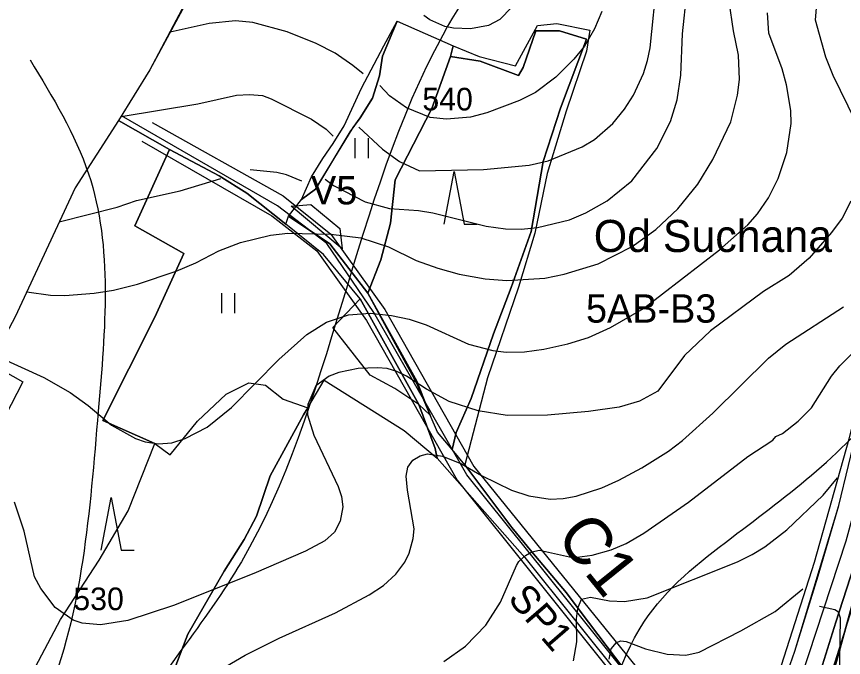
# Model space of a CAD drawing. Extents: x -684583 to -680383, y -1157874 to -1154904.
# Drawn here: x -683060.3 to -682621.9, y -1155712.7 to -1155373 of the extents above; entities that cross this region are included whole.
import ezdxf

# ---------------------------------------------------------------- set-up
doc = ezdxf.new("R2010")
doc.units = 0
for name, color, linetype in [('01_DOPRAVA', 7, 'Continuous'), ('01_MÍSTNÍ_NÁZVY', 7, 'Continuous'), ('01_OBVOD PÚ', 7, 'Continuous'), ('01_SPRÁV_HRANICE', 7, 'Continuous'), ('01_VRSTEVNICE', 7, 'Continuous'), ('02_KULTURY STAV', 7, 'Continuous'), ('03_PC_OBJEKTY_NÁVRH', 7, 'Continuous'), ('03_PC_POPIS_STAV', 7, 'Continuous'), ('03_PC_STAV', 7, 'Continuous'), ('05_VHO_MELIORACE', 7, 'Continuous'), ('06_BIOGEOGRAFIE', 7, 'Continuous'), ('06_ÚSES_IP', 7, 'Continuous')]:
    doc.layers.add(name, color=color, linetype=linetype)

msp = doc.modelspace()

# ---------------------------------------------------------------- linework, layer by layer
at = {"layer": '01_DOPRAVA'}
msp.add_lwpolyline([(-682444.78, -1155001.44), (-682484.97, -1155081.41), (-682523.81, -1155212.27), (-682554.69, -1155333.36), (-682575.58, -1155465.36), (-682603.29, -1155587.36), (-682620.55, -1155650.97), (-682668.34, -1155796.22), (-682702.3, -1155906.34), (-682764.53, -1156097.63), (-682782.62, -1156147.93)], dxfattribs=at)
at = {"layer": '01_OBVOD PÚ'}
msp.add_lwpolyline([(-682967.81, -1155360.67), (-682989.69, -1155401.27), (-683006.2, -1155428.07), (-683029.21, -1155463.74), (-683061.11, -1155532.25)], dxfattribs=at)
at = {"layer": '01_SPRÁV_HRANICE'}
msp.add_lwpolyline([(-682967.81, -1155360.67), (-682989.69, -1155401.27), (-683006.2, -1155428.07), (-683029.21, -1155463.74), (-683061.11, -1155532.25)], dxfattribs=at)
at = {"layer": '01_VRSTEVNICE'}
for points in [[(-682878.89, -1155431.61), (-682866.34, -1155443.3), (-682857.21, -1155449.86), (-682846.65, -1155454.71), (-682812.7, -1155454), (-682788.45, -1155451.72), (-682778.47, -1155449.58), (-682760.49, -1155442.02), (-682753.79, -1155438.17), (-682744.23, -1155429.75), (-682737.96, -1155422.19), (-682733.11, -1155414.63), (-682727.83, -1155403.22), (-682725.69, -1155396.37), (-682724.41, -1155389.53), (-682720.7, -1155353.01)], [(-682896.72, -1155459.28), (-682892.3, -1155462.56), (-682875.47, -1155471.26), (-682862.63, -1155474.68), (-682847.22, -1155475.82), (-682839.52, -1155477.11), (-682811.28, -1155484.1), (-682801.01, -1155485.53), (-682792.73, -1155485.67), (-682784.17, -1155484.81), (-682767.06, -1155480.82), (-682758.5, -1155477.11), (-682747.09, -1155470.69), (-682734.1, -1155460.13), (-682720.84, -1155442.88), (-682713.57, -1155428.61), (-682710, -1155417.2), (-682708.14, -1155404.08), (-682707.15, -1155382.11), (-682704.86, -1155360.43)], [(-683054.89, -1155518.9), (-683042.36, -1155520.76), (-683034.66, -1155520.9), (-683019.25, -1155519.62), (-683008.98, -1155518.05), (-682996.14, -1155514.91), (-682975.6, -1155507.92), (-682965.33, -1155503.5), (-682953.06, -1155497.22), (-682941.65, -1155492.8), (-682925.68, -1155488.81), (-682916.55, -1155487.81), (-682893.72, -1155488.38), (-682877.75, -1155490.23), (-682863.06, -1155495.08), (-682848.36, -1155502.36), (-682836.95, -1155506.35), (-682825.54, -1155509.49), (-682811.85, -1155512.06), (-682800.43, -1155512.91), (-682780.18, -1155511.63), (-682769.91, -1155509.49), (-682751.94, -1155504.07), (-682733.96, -1155494.94), (-682721.27, -1155485.95), (-682709.71, -1155474.97), (-682699.01, -1155461.85), (-682691.17, -1155448.87), (-682681.61, -1155428.9), (-682678.05, -1155414.63), (-682676.91, -1155406.36), (-682677.48, -1155393.52), (-682680.19, -1155380.68), (-682682.47, -1155364.99)], [(-682749.94, -1155370.41), (-682753.79, -1155379.54), (-682759.21, -1155388.67), (-682764.77, -1155395.66), (-682774.33, -1155405.07), (-682785.17, -1155413.21), (-682793.59, -1155417.48), (-682810.99, -1155424.05), (-682819.55, -1155426.33), (-682832.39, -1155427.47), (-682840.95, -1155426.47), (-682853.5, -1155421.33), (-682862.48, -1155415.06), (-682867.62, -1155409.5)], [(-682797.72, -1155367.99), (-682804.14, -1155374.55), (-682810.13, -1155377.69), (-682819.55, -1155379.54), (-682828.68, -1155379.26), (-682833.24, -1155378.26), (-682841.23, -1155374.83), (-682844.37, -1155372.55)], [(-682800.72, -1155550.86), (-682791.02, -1155550.71), (-682780.75, -1155549.29), (-682768.05, -1155546.43), (-682757.07, -1155543.15), (-682745.37, -1155537.88), (-682727.97, -1155527.75), (-682687.6, -1155496.65), (-682672.63, -1155483.39), (-682667.49, -1155477.54), (-682661.64, -1155469.12), (-682656.51, -1155458.85), (-682651.94, -1155445.16), (-682649.52, -1155429.75), (-682649.8, -1155422.9), (-682652.08, -1155409.21), (-682654.37, -1155400.65), (-682661.36, -1155381.82), (-682662.07, -1155370.98)], [(-682636.25, -1155368.56), (-682636.82, -1155374.83), (-682631.4, -1155394.38), (-682627.41, -1155404.08), (-682615.71, -1155428.32)], [(-682876.57, -1155403.42), (-682881.92, -1155398.9), (-682891.3, -1155392.38), (-682901.43, -1155387.24), (-682916.83, -1155381.11), (-682935.09, -1155376.26), (-682944.22, -1155375.26), (-682958.2, -1155376.69), (-682978.9, -1155381.25)], [(-683004.92, -1155425.98), (-682964.19, -1155419.34), (-682943.65, -1155414.77), (-682936.8, -1155414.35), (-682929.96, -1155414.92), (-682925.39, -1155416.63), (-682903.85, -1155427.47), (-682896.15, -1155432.75), (-682892.44, -1155436.46)], [(-682908.99, -1155460.28), (-682917.12, -1155457), (-682922.25, -1155455.71), (-682936.38, -1155454.29)], [(-683037.65, -1155481.88), (-683006.98, -1155474.11), (-682996.71, -1155470.55), (-682973.6, -1155465.41), (-682952.07, -1155458.85)], [(-682617.99, -1155470.83), (-682622.56, -1155479.96), (-682628.12, -1155487.52), (-682640.1, -1155501.07), (-682650.66, -1155510.35), (-682664.21, -1155518.76), (-682692.29, -1155539.65), (-682706.15, -1155552.71), (-682720.27, -1155571.54), (-682729.97, -1155576.82), (-682740.81, -1155579.96), (-682757.07, -1155582.38), (-682778.75, -1155584.23), (-682800.15, -1155584.38), (-682815.55, -1155581.95), (-682830.96, -1155577.1), (-682842.94, -1155570.54), (-682853.5, -1155563.69), (-682858.63, -1155561.13), (-682863.77, -1155559.56), (-682868.9, -1155559.13), (-682879.17, -1155559.56), (-682889.45, -1155561.7), (-682894.58, -1155563.69), (-682901.57, -1155568.69), (-682905.85, -1155578.67), (-682905.99, -1155584.09), (-682902.71, -1155594.93), (-682889.73, -1155622.04), (-682888.02, -1155627.46), (-682887.3, -1155632.88), (-682888.64, -1155640.39), (-682891.73, -1155646.36), (-682896.87, -1155650.89), (-682907.13, -1155656.41), (-682934.52, -1155668.11), (-682977.03, -1155685.08), (-683001.28, -1155693.07), (-683015.83, -1155695.35), (-683025.53, -1155694.5), (-683030.38, -1155692.93), (-683039.79, -1155686.23), (-683047.49, -1155676.1), (-683050.78, -1155669.96), (-683056.2, -1155645.71), (-683061.47, -1155630.31)], [(-682964.76, -1155726.45), (-682939.08, -1155711.47), (-682921.11, -1155702.49), (-682891.16, -1155689.08), (-682873.33, -1155679.52), (-682865.77, -1155674.53), (-682859.2, -1155668.54), (-682854.5, -1155662.26), (-682852.07, -1155657.41), (-682849.93, -1155649.71), (-682849.5, -1155644.57), (-682853.07, -1155624.03), (-682853.64, -1155616.61), (-682852.93, -1155611.76), (-682850.22, -1155608.06), (-682846.37, -1155605.77), (-682842.37, -1155604.78), (-682834.38, -1155606.06), (-682824.4, -1155610.05), (-682813.84, -1155616.19), (-682797.87, -1155624.03), (-682788.74, -1155627.03), (-682777.33, -1155628.88), (-682770.48, -1155628.46), (-682763.63, -1155627.17), (-682749.94, -1155622.75), (-682740.95, -1155618.75), (-682728.68, -1155612.19), (-682714.71, -1155603.35), (-682707.15, -1155597.64), (-682691.17, -1155583.24), (-682661.64, -1155554.14), (-682652.37, -1155546.58), (-682621.84, -1155526.89)], [(-683072, -1155552.54), (-683045.78, -1155564.26), (-683031.95, -1155572.25), (-683022.39, -1155579.24), (-683009.98, -1155589.51), (-682997.28, -1155596.64), (-682992.15, -1155598.36), (-682985.02, -1155599.5), (-682978.03, -1155598.93), (-682970.89, -1155596.64), (-682959.2, -1155590.65), (-682946.36, -1155580.24), (-682921.25, -1155554.85), (-682906.42, -1155541.58), (-682896.01, -1155535.02), (-682884.31, -1155531.03), (-682872.9, -1155530.17), (-682861.49, -1155531.46), (-682852.21, -1155533.45), (-682843.08, -1155536.45), (-682820.69, -1155546.58), (-682807.85, -1155550), (-682800.72, -1155550.86)], [(-682833.67, -1155714.75), (-682822.26, -1155706.62), (-682811.56, -1155695.5), (-682803.72, -1155683.37), (-682795.3, -1155663.97), (-682794.02, -1155661.83), (-682790.45, -1155658.7), (-682787.03, -1155656.7), (-682783.03, -1155655.84), (-682767.06, -1155659.27), (-682763.06, -1155659.55), (-682755.07, -1155658.55), (-682745.09, -1155655.7), (-682737.1, -1155652.28), (-682727.69, -1155646.86), (-682704.01, -1155630.31), (-682672.63, -1155606.2), (-682659.36, -1155597.5), (-682657.65, -1155595.65), (-682654.22, -1155594.08), (-682645.81, -1155587.52), (-682638.82, -1155580.38), (-682628.12, -1155563.55), (-682623.84, -1155558.13), (-682614.57, -1155549)], [(-682764.92, -1155714.47), (-682763.2, -1155704.48), (-682763.49, -1155692.22), (-682762.78, -1155686.65), (-682760.78, -1155681.8), (-682755.93, -1155680.66), (-682745.95, -1155682.66), (-682737.96, -1155682.95), (-682725.97, -1155681.09), (-682678.05, -1155661.98), (-682670.2, -1155658.12), (-682663.5, -1155653.99), (-682651.94, -1155645), (-682632.67, -1155626.7), (-682625.05, -1155617.54)], [(-682746.07, -1155713.51), (-682745.09, -1155708.19), (-682742.24, -1155704.77), (-682739.95, -1155703.91), (-682737.1, -1155704.2), (-682726.83, -1155708.19), (-682715.42, -1155710.9), (-682705.43, -1155711.47), (-682698.44, -1155709.9), (-682676.19, -1155698.63), (-682658.08, -1155688.36), (-682643.38, -1155676.24)], [(-682623.98, -1155726.45), (-682623.41, -1155691.93), (-682624.41, -1155688.65), (-682626.41, -1155687.51), (-682634.54, -1155685.65)]]:
    msp.add_lwpolyline(points, dxfattribs=at)
at = {"layer": '02_KULTURY STAV'}
for points in [[(-682954.04, -1155334.16), (-682989.69, -1155401.27), (-683006.2, -1155428.07), (-682979.18, -1155443.54), (-682952.96, -1155457.49), (-682938.17, -1155466.61), (-682917.62, -1155483.01), (-682916.12, -1155478.76), (-682909.29, -1155470.06), (-682903.85, -1155457.96), (-682897.92, -1155448.34), (-682892.38, -1155440.35), (-682886.65, -1155430.96), (-682877.39, -1155410.94), (-682865.59, -1155388.54), (-682858.57, -1155375.5), (-682828.85, -1155388.48), (-682815.01, -1155394.17), (-682795.71, -1155399.1), (-682784.17, -1155377.72), (-682773.85, -1155376.65), (-682756.27, -1155380.27), (-682758.16, -1155391.39), (-682768.88, -1155423.13), (-682778.99, -1155456.14), (-682785.42, -1155487.75), (-682794.08, -1155516.53), (-682810.62, -1155564.48), (-682822.56, -1155610.59), (-682797.64, -1155643.87), (-682787.07, -1155656.7), (-682768.66, -1155678.49), (-682761.91, -1155687.44), (-682732.92, -1155725.98)], [(-682666.12, -1155762.26), (-682647.64, -1155709.29), (-682635.27, -1155669.44), (-682624.39, -1155632.23), (-682608.85, -1155568.57), (-682591.9, -1155497.49), (-682584.57, -1155462.64), (-682579.29, -1155422.44), (-682571.28, -1155382.11), (-682563.38, -1155332.6)], [(-682647.1, -1155761.89), (-682625.87, -1155693.99), (-682606.64, -1155634.44), (-682588.52, -1155559.14), (-682573.81, -1155489.54), (-682560.88, -1155424.9), (-682555.58, -1155385.09), (-682547.5, -1155336.35)], [(-682880.89, -1155437.5), (-682880.89, -1155448)], [(-682873.89, -1155437.5), (-682873.89, -1155448)], [(-682833.51, -1155483.12), (-682828.26, -1155455.12), (-682823.01, -1155483.12), (-682816.01, -1155483.12)], [(-682951.69, -1155519.68), (-682951.69, -1155530.18)], [(-682944.69, -1155519.68), (-682944.69, -1155530.18)], [(-683071.96, -1155758.47), (-683036.98, -1155692.61), (-683016.49, -1155661.06), (-683001.08, -1155634.9), (-682987.04, -1155599.33), (-682978.82, -1155605.29), (-682964.38, -1155587.46), (-682949.14, -1155573.18), (-682937.1, -1155567.23), (-682928.26, -1155568.38), (-682918.9, -1155575.81), (-682905.95, -1155580.31), (-682908.17, -1155584.07), (-682925.77, -1155616.37), (-682933.16, -1155637.77), (-682939.57, -1155650.2), (-682950.3, -1155666.9), (-682969.44, -1155700.39), (-682979.06, -1155725.2)], [(-682979.06, -1155725.2), (-682969.44, -1155700.39), (-682950.3, -1155666.9), (-682939.57, -1155650.2), (-682933.16, -1155637.77), (-682925.77, -1155616.37), (-682908.17, -1155584.07), (-682905.95, -1155580.31), (-682897.16, -1155565.78), (-682854.81, -1155592.4), (-682837.34, -1155607.06), (-682790.82, -1155659.69), (-682738.18, -1155725.49)], [(-682732.92, -1155725.98), (-682761.91, -1155687.44), (-682768.66, -1155678.49), (-682787.07, -1155656.7), (-682797.64, -1155643.87), (-682822.56, -1155610.59), (-682829.33, -1155602.46), (-682837.2, -1155593.25), (-682841.07, -1155584.34), (-682846.93, -1155578.71), (-682838.42, -1155601.92), (-682837.34, -1155607.06), (-682790.82, -1155659.69), (-682738.18, -1155725.49)], [(-683015.39, -1155655.88), (-683010.14, -1155627.88), (-683004.89, -1155655.88), (-682997.89, -1155655.88)]]:
    msp.add_lwpolyline(points, dxfattribs=at)
for points in [[(-682916.12, -1155478.76), (-682909.29, -1155470.06), (-682901.75, -1155464.5), (-682881.77, -1155431.91), (-682878.07, -1155426.74), (-682871.6, -1155416.23), (-682867.92, -1155404.41), (-682866.24, -1155394.03), (-682858.57, -1155375.5), (-682828.85, -1155388.48), (-682830.3, -1155394.17), (-682840.04, -1155421.84), (-682859.63, -1155459.54), (-682862.07, -1155482.53), (-682867.24, -1155501.94), (-682874.12, -1155519.66), (-682894.27, -1155493.44)], [(-682909.29, -1155470.06), (-682903.85, -1155457.96), (-682897.92, -1155448.34), (-682892.38, -1155440.35), (-682886.65, -1155430.96), (-682877.39, -1155410.94), (-682865.59, -1155388.54), (-682858.57, -1155375.5), (-682866.24, -1155394.03), (-682867.92, -1155404.41), (-682871.6, -1155416.23), (-682878.07, -1155426.74), (-682883.58, -1155434.11), (-682901.75, -1155464.5)], [(-682874.12, -1155519.66), (-682867.24, -1155501.94), (-682862.07, -1155482.53), (-682859.63, -1155459.54), (-682840.04, -1155421.84), (-682830.3, -1155394.17), (-682814.42, -1155396.76), (-682794.15, -1155404.21), (-682791.67, -1155399.99), (-682784.97, -1155380.62), (-682772.46, -1155380.6), (-682758.19, -1155385.09), (-682771.9, -1155421.59), (-682781.06, -1155449.84), (-682787.39, -1155486.89), (-682798.02, -1155516.55), (-682807.46, -1155541.18), (-682819.23, -1155575.44), (-682827.24, -1155593.45), (-682829.33, -1155602.46), (-682837.2, -1155593.25), (-682841.07, -1155584.34), (-682848.11, -1155567.58)], [(-682787.39, -1155486.89), (-682781.06, -1155449.84), (-682771.9, -1155421.59), (-682758.19, -1155385.09), (-682772.46, -1155380.6), (-682784.97, -1155380.62), (-682791.67, -1155399.99), (-682794.15, -1155404.21), (-682814.42, -1155396.76), (-682830.3, -1155394.17), (-682828.85, -1155388.48), (-682815.01, -1155394.17), (-682795.71, -1155399.1), (-682784.17, -1155377.72), (-682773.85, -1155376.65), (-682756.27, -1155380.27), (-682758.16, -1155391.39), (-682768.88, -1155423.13), (-682778.99, -1155456.14), (-682785.42, -1155487.75), (-682794.08, -1155516.53), (-682810.62, -1155564.48), (-682822.56, -1155610.59), (-682829.33, -1155602.46), (-682827.24, -1155593.45), (-682819.23, -1155575.44), (-682807.46, -1155541.18), (-682798.02, -1155516.55)], [(-683006.2, -1155428.07), (-683029.21, -1155463.74), (-683061.11, -1155532.25), (-683074.32, -1155556.93), (-683056.98, -1155566.65), (-683066.36, -1155584.79), (-683075.11, -1155604.61), (-683083.75, -1155622.56), (-683084.97, -1155630.7), (-683075.94, -1155646.03), (-683105.92, -1155700.14), (-683119.61, -1155729.12), (-683095.22, -1155742), (-683081.21, -1155752.78), (-683071.96, -1155758.47), (-683036.98, -1155692.61), (-683016.49, -1155661.06), (-683001.08, -1155634.9), (-682987.04, -1155599.33), (-683014.5, -1155587.07), (-682986.93, -1155532.32), (-682971.59, -1155498.53), (-682997.53, -1155483.87), (-682979.18, -1155443.54)], [(-682979.18, -1155443.54), (-682997.53, -1155483.87), (-682971.59, -1155498.53), (-682986.93, -1155532.32), (-683014.5, -1155587.07), (-682987.04, -1155599.33), (-682978.82, -1155605.29), (-682964.38, -1155587.46), (-682949.14, -1155573.18), (-682937.1, -1155567.23), (-682928.26, -1155568.38), (-682918.9, -1155575.81), (-682905.95, -1155580.31), (-682897.16, -1155565.78), (-682854.81, -1155592.4), (-682837.34, -1155607.06), (-682838.42, -1155601.92), (-682846.93, -1155578.71), (-682859.75, -1155570.09), (-682872.89, -1155563.1), (-682892.53, -1155537.74), (-682878.12, -1155522.68), (-682897.55, -1155499.16), (-682917.62, -1155483.01), (-682938.17, -1155466.61), (-682952.96, -1155457.49)], [(-682916.12, -1155478.76), (-682894.27, -1155493.44), (-682874.12, -1155519.66), (-682848.11, -1155566.21), (-682841.07, -1155584.34), (-682846.93, -1155578.71), (-682878.12, -1155522.68), (-682897.55, -1155499.16), (-682917.62, -1155483.01)], [(-682878.12, -1155522.68), (-682846.93, -1155578.71), (-682859.75, -1155570.09), (-682872.89, -1155563.1), (-682892.53, -1155537.74)], [(-683074.32, -1155556.93), (-683056.98, -1155566.65), (-683066.36, -1155584.79), (-683075.11, -1155604.61), (-683083.75, -1155622.56), (-683084.97, -1155630.7), (-683075.94, -1155646.03), (-683105.92, -1155700.14), (-683111.72, -1155711.48), (-683119.61, -1155729.12), (-683165.53, -1155720.57), (-683142.13, -1155679.03), (-683095.74, -1155596.78), (-683078.81, -1155565.36)], [(-682742.95, -1156008.33), (-682720.91, -1155937.51), (-682700.78, -1155875.54), (-682679.31, -1155800.06), (-682676.88, -1155793.28), (-682675.23, -1155788.62), (-682672.99, -1155782.95), (-682666.12, -1155762.26), (-682647.64, -1155709.29), (-682624.39, -1155632.23), (-682608.85, -1155568.57), (-682588.52, -1155559.14), (-682606.64, -1155634.44), (-682625.87, -1155693.99), (-682647.1, -1155761.89), (-682657.41, -1155794.38), (-682661.35, -1155805), (-682697.27, -1155915.21), (-682725.67, -1156001.43)]]:
    msp.add_lwpolyline(points, close=True, dxfattribs=at)
at = {"layer": '03_PC_OBJEKTY_NÁVRH'}
for points in [[(-682988.48, -1155429.24), (-682918.93, -1155468.13), (-682893.72, -1155488.38), (-682865.08, -1155528.33), (-682817.78, -1155611.5), (-682731.85, -1155717.62), (-682691.81, -1155756.51), (-682678.23, -1155771.5)], [(-682993.86, -1155439.08), (-682925.02, -1155478.67), (-682901.14, -1155497.18), (-682874.68, -1155534.19), (-682826.68, -1155618.76), (-682742.86, -1155723.24), (-682700.24, -1155766.11), (-682676.88, -1155793.28)]]:
    msp.add_lwpolyline(points, dxfattribs=at)
msp.add_lwpolyline([(-682914.77, -1155473.55), (-682904.21, -1155472.6), (-682888.86, -1155485.42), (-682887.71, -1155496.15)], close=True, dxfattribs=at)
at = {"layer": '03_PC_STAV'}
msp.add_lwpolyline([(-682668.28, -1155790.37), (-682685.83, -1155773.73), (-682696.52, -1155760.91), (-682735.97, -1155722.42), (-682821.6, -1155615.88), (-682870.86, -1155529.79), (-682895.8, -1155493.35), (-682921.9, -1155473.38), (-683004.74, -1155425.7)], dxfattribs=at)
at = {"layer": '05_VHO_MELIORACE'}
msp.add_line((-682635.04, -1155749.47), (-682580.41, -1155551.03), dxfattribs=at)
msp.add_lwpolyline([(-682635.04, -1155749.47), (-682580.41, -1155551.03), (-682535.85, -1155325.07)], dxfattribs=at)
at = {"layer": '06_BIOGEOGRAFIE'}
for points in [[(-682624.87, -1154935.44), (-682669.05, -1155140.04), (-682739.65, -1155253.72), (-682834.36, -1155382.91), (-682941.12, -1155661.96), (-683008.28, -1155760.14), (-683056.49, -1155810.09), (-683084.04, -1155808.37), (-683154.45, -1155886.49), (-683231.94, -1156062.19), (-683280.08, -1156211.64), (-683362.74, -1156430.39), (-683497.05, -1156731.83), (-683541.82, -1156781.78), (-683638.25, -1156792.12), (-683701.96, -1156768), (-683817.33, -1156693.94)], [(-682856.86, -1155847.34), (-682791.42, -1155830.12), (-682727.71, -1155694.04), (-682681.22, -1155649.25), (-682596.84, -1155571.74), (-682571.01, -1155502.84), (-682602.01, -1155421.88), (-682614.06, -1155356.43), (-682565.85, -1155299.59), (-682515.91, -1155292.7)], [(-683053.16, -1155396.05), (-683022.17, -1155456.33), (-683017, -1155582.08), (-683044.55, -1155735.38), (-683087.6, -1155812.89)]]:
    msp.add_spline(points, degree=3, dxfattribs=at)
at = {"layer": '06_ÚSES_IP'}
for points in [[(-682530.18, -1155187.74), (-682556.31, -1155287.32), (-682580.65, -1155417.4), (-682596.62, -1155505.37), (-682619.02, -1155596.96), (-682637.3, -1155662.36), (-682672.55, -1155772.07), (-682712.43, -1155905.02), (-682772.45, -1156078.06), (-682846.1, -1156262.2), (-682899.06, -1156383.28), (-682928.82, -1156472.07), (-682968.71, -1156622.54), (-683017.6, -1156838.34)], [(-683045.5, -1156945.1), (-682993.87, -1156850.83), (-682970.35, -1156763.63), (-682943.14, -1156635.49), (-682907.69, -1156485.87), (-682877.43, -1156403.71), (-682855.81, -1156343.74), (-682797.01, -1156219.49), (-682773.09, -1156158.67), (-682722.07, -1156008.47), (-682663.84, -1155833.77), (-682598.99, -1155629.09), (-682554.6, -1155429.31), (-682533.56, -1155299)]]:
    msp.add_lwpolyline(points, dxfattribs=at)

# ---------------------------------------------------------------- texts
at = {"layer": '01_MÍSTNÍ_NÁZVY'}
msp.add_text('Od Suchana', height=17, dxfattribs=at).set_placement((-682754.25, -1155497.82))
at = {"layer": '01_VRSTEVNICE'}
for s, p in [('540', (-682845.15, -1155422.8)), ('530', (-683030.22, -1155687.63))]:
    msp.add_text(s, height=12, dxfattribs=at).set_placement(p)
at = {"layer": '03_PC_OBJEKTY_NÁVRH'}
msp.add_text('V5', height=15, dxfattribs=at).set_placement((-682904.21, -1155472.6))
msp.add_text('SP1', height=15, rotation=310.8041, dxfattribs=at).set_placement((-682800.34, -1155681.85))
at = {"layer": '03_PC_POPIS_STAV'}
msp.add_text('C1', height=25, rotation=308.7903, dxfattribs=at).set_placement((-682774.92, -1155648.97))
at = {"layer": '06_BIOGEOGRAFIE'}
msp.add_text('5AB-B3', height=15, dxfattribs=at).set_placement((-682758.38, -1155535.26))

doc.saveas('drawing.dxf')
